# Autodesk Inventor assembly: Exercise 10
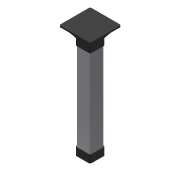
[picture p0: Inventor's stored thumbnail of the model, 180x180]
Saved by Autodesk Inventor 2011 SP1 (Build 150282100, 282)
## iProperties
Created: 2011-02
Part Number: Exercise 10
Document SubType Name: Assembly
Designer: SERGIO
Author: SERGIO
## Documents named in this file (4)
- C:\Users\sergio.duran\Documents\IAC\ACADDEMIA\EVALUACIONES\Autodesk Inventor Proficiency\Exercise 10.iam
- C:\Users\sergio.duran\Documents\IAC\ACADDEMIA\EVALUACIONES\Autodesk Inventor Proficiency\Exercise 10\ISO 4019 - 400x400x10 - 0,001.ipt
- C:\Users\sergio.duran\Documents\IAC\ACADDEMIA\EVALUACIONES\Autodesk Inventor Proficiency\KRT-01.ipt
- C:\Users\sergio.duran\Documents\IAC\ACADDEMIA\EVALUACIONES\Autodesk Inventor Proficiency\KRT-02.ipt
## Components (3 placed, 3 different names)
1. ISO 4019 - 100x100x3 - 800:1 — Flush:1, Flush:2, Mate:1, Mate:2
2. KRT-01:1 — Flush:1
3. KRT-02:1 — Flush:2, Mate:1, Mate:2
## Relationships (4: Flush 2, Mate 2)
- Flush:1: ISO 4019 - 100x100x3 - 800:1 ↔ KRT-01:1
- Flush:2: ISO 4019 - 100x100x3 - 800:1 ↔ KRT-02:1
- Mate:1: ISO 4019 - 100x100x3 - 800:1 ↔ KRT-02:1
- Mate:2: ISO 4019 - 100x100x3 - 800:1 ↔ KRT-02:1
